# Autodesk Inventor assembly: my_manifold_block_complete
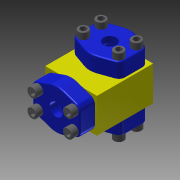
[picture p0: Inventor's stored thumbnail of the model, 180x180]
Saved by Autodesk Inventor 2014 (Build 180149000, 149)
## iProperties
Created: 2009-02
Part Number: my_manifold_block_complete
Document SubType Name: Assembly
Designer: pekj
RuleStatus: InUse
Author: pekj
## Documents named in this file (6)
- C:\Users\iTools\Desktop\tutorial files\iLogic\my_manifold_block_complete.iam
- D:\ilogic-mystique-rel\Tutorials\union_cap.ipt
- D:\ilogic-mystique-rel\Tutorials\Screw.ipt
- C:\Users\iTools\Desktop\tutorial files\iLogic\manifold_block_complete.ipt
- C:\Users\iTools\Desktop\tutorial files\iLogic\union_cap\union_cap [Model Code=100].ipt
- C:\Users\iTools\Desktop\tutorial files\iLogic\SHCS\Screw-02.ipt
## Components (16 placed, 8 different names)
1. manifold_block:1 — port_a_cap_center, port_a_cap_hole, port_a_cap_face, port_b_cap_center, port_b_cap_hole, port_b_cap_face, port_c_cap_center, port_c_cap_hole, port_c_cap_face
2. port_a_union — port_a_cap_center, port_a_cap_face, port_a_cap_screw, port_a_cap_hole
3. port_b_union — port_b_cap_center, port_b_cap_face, port_b_cap_screw, port_b_cap_hole
4. port_c_union — port_c_cap_center, port_c_cap_face, port_c_cap_screw, port_c_cap_hole
5. port_a_union_screw — port_a_cap_screw
6. Screw-02:4
7. Screw-02:5
8. Screw-02:6
9. port_b_union_screw — port_b_cap_screw
10. Screw-02:7
11. Screw-02:8
12. Screw-02:9
13. port_c_union_screw — port_c_cap_screw
14. Screw-02:10
15. Screw-02:11
16. Screw-02:12
## Component patterns: port_a_screw_pattern (4 elements), port_b_screw_pattern (4 elements), port_c_screw_pattern (4 elements)
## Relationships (12: Mate 9, Insert 3)
- port_a_cap_center [Mate]: manifold_block:1 ↔ port_a_union
- port_a_cap_hole [Mate]: manifold_block:1 ↔ port_a_union
- port_a_cap_face [Mate]: manifold_block:1 ↔ port_a_union
- port_a_cap_screw [Insert]: port_a_union ↔ port_a_union_screw
- port_b_cap_center [Mate]: manifold_block:1 ↔ port_b_union
- port_b_cap_hole [Mate]: manifold_block:1 ↔ port_b_union
- port_b_cap_face [Mate]: manifold_block:1 ↔ port_b_union
- port_b_cap_screw [Insert]: port_b_union ↔ port_b_union_screw
- port_c_cap_center [Mate]: manifold_block:1 ↔ port_c_union
- port_c_cap_hole [Mate]: manifold_block:1 ↔ port_c_union
- port_c_cap_face [Mate]: manifold_block:1 ↔ port_c_union
- port_c_cap_screw [Insert]: port_c_union ↔ port_c_union_screw
## Named parameters: port_a_y_dist_between_screws = 26.162 mm, port_a_x_dist_between_screws = 52.324 mm, port_b_y_dist_between_screws = 26.162 mm, port_b_x_dist_between_screws = 52.324 mm, port_c_y_dist_between_screws = 26.162 mm, port_c_x_dist_between_screws = 52.324 mm
